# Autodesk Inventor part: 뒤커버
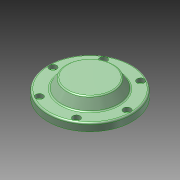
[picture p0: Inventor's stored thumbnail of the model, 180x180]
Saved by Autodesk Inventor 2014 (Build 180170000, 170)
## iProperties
Created: 2013-01
Part Number: 뒤커버
Document SubType Name: Modeling
Designer: 한국산업디자인학원[gmhk.co.kr]
Density: 2.71 g/cm^3
Material: 알루미늄 6061
Mass: 415.969 g
Surface Area: 272.105 cm^2
Volume: 153.494 cm^3
Appearance: 알루미늄 - 평지(1)
Author: 한국산업디자인학원[gmhk.co.kr]
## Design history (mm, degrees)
sketch "스케치2"
  geometry: L1 (-55, 0)-(55, 0) reference; L2 (35.98, -6)-(-35.98, -6) reference; L3 (-42.5, -25)-(-42.5, 0) reference; L4 (-37, -6)-(-37, 0); L5 (-55, 0)-(-55, 10); L6 (-55, 10)-(-37.5, 10); L7 (-37, -6)-(-42.5, -6); L8 (-37.5, 10)-(-29.994, 23); L9 (-29.994, 23)-(0, 23); L10 (-55, 0)-(-42.5, 0); L11 (-42.5, -6)-(-42.5, 0); L12 (0, 0)-(0, 23); L13 (0, 0)-(-37, 0)
  constraints: 22 end point, 4 perpendicular, 3 collinear, 2 parallel, 2 point on line, 1 vertical, 2 other
  dimensions: "d2" = 10 distance of L1.start L5.end; "d4" = 120 deg angle of L8 L6; "d5" = 13 distance between parallel lines of L6 L9; "d6" = 74 diameter of L4 L12; "d7" = 75 diameter of L6.end L12
revolve "회전1" sketch "스케치2" stored, may be unused: angle "d8" = 90 deg
fillet "모깎기1" dims "d9" = 2
sketch "스케치3"
  geometry: C1 r 2.067 at (48.5, 0) reference; 1 further point
hole "구멍1" sketch "스케치3" at (48.5, 0) diameter "d10" = 5.5; stored, may be unused: countersink angle "d14" = 90 deg, drill point angle "d16" = 118 deg; dims "d11" = 6, "d12" = 9.5, "d13" = 5.4, "d15" = 8
fillet "모깎기2" dims "d20" = 3
chamfer "모따기1" distance "d21" = 1; stored, may be unused: second distance "d22" = 2, angle "d23" = 45 deg
node "솔리드1"
pattern_circular "원형 패턴1" dims angle "d18" = 360 deg
node "참조1"
node "참조2"
node "참조3"
